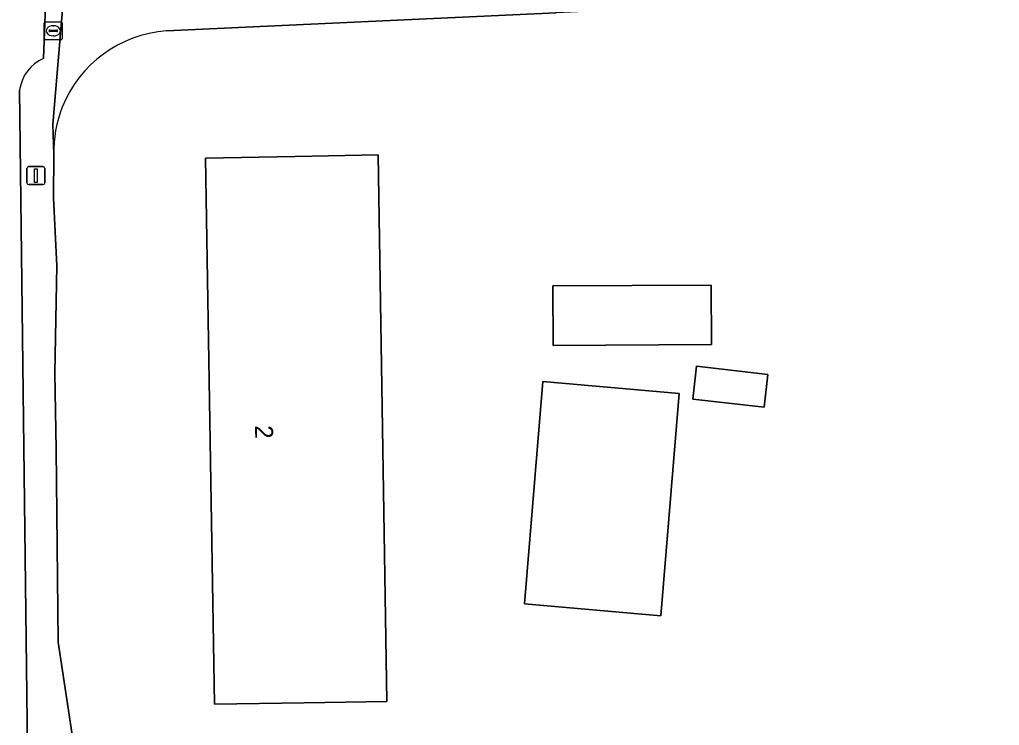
# Model space of a CAD drawing. Extents: x 163859 to 164644, y 379566 to 382155.
# Drawn here: x 164443.9 to 164498.5, y 381567 to 381606.4 of the extents above; entities that cross this region are included whole.
import ezdxf

# ---------------------------------------------------------------- set-up
doc = ezdxf.new("R2010")
doc.units = 0
for name, color, linetype in [('IMGEO_Brandkraan', 7, 'Continuous'), ('IMGEO_Erf', 7, 'Continuous'), ('IMGEO_Groenvoorziening', 7, 'Continuous'), ('IMGEO_Lichtmast', 7, 'Continuous'), ('IMGEO_Pand', 7, 'Continuous'), ('IMGEO_Pand_nummerreeks', 7, 'Continuous'), ('IMGEO_Rijbaan_lokaal_gesloten', 7, 'Continuous')]:
    doc.layers.add(name, color=color, linetype=linetype)

msp = doc.modelspace()

# ---------------------------------------------------------------- linework, layer by layer
at = {"layer": 'IMGEO_Brandkraan'}
for p, q in [((164445.336, 381606.254), (164446.188, 381606.254)), ((164445.261, 381605.328), (164445.261, 381606.18)), ((164445.52, 381605.748), (164445.52, 381605.76)), ((164445.958, 381605.711), (164445.56, 381605.711)), ((164445.563, 381605.797), (164445.961, 381605.797)), ((164445.749, 381606.034), (164445.774, 381606.034)), ((164446.004, 381605.76), (164446.004, 381605.748)), ((164446.262, 381606.18), (164446.262, 381605.328)), ((164446.188, 381605.254), (164445.336, 381605.254)), ((164445.772, 381605.474), (164445.747, 381605.474))]:
    msp.add_line(p, q, dxfattribs=at)
for points in [[(164445.336, 381606.254), (164446.188, 381606.254)], [(164445.261, 381605.328), (164445.261, 381606.18)], [(164446.262, 381606.18), (164446.262, 381605.328)], [(164446.188, 381605.254), (164445.336, 381605.254)]]:
    msp.add_lwpolyline(points, dxfattribs=at)
for centre, radius, start, end in [((164445.338, 381606.178), 0.0765, 91.552, 178.448), ((164445.338, 381606.178), 0.0765, 91.552, 178.448), ((164446.186, 381606.178), 0.0765, 1.552, 88.448), ((164446.186, 381606.178), 0.0765, 1.552, 88.448), ((164445.56, 381605.757), 0.0403, 85.8775, 175.7526), ((164445.557, 381605.747), 0.0366, 178.938, 274.7102), ((164445.961, 381605.754), 0.043, 264.8664, 352.4533), ((164445.965, 381605.759), 0.0386, 1.7309, 96.639), ((164445.338, 381605.33), 0.0765, 181.552, 268.448), ((164445.338, 381605.33), 0.0765, 181.552, 268.448), ((164446.186, 381605.33), 0.0765, 271.552, 358.448), ((164446.186, 381605.33), 0.0765, 271.552, 358.448)]:
    msp.add_arc(centre, radius, start, end, dxfattribs=at)
for centre, major_axis, ratio, start_param, end_param in [((164445.748, 381605.754), (-0.387, 0.002), 0.722429, 4.712389, 7.853982), ((164445.773, 381605.754), (-0.39, 0.002), 0.717154, 1.570796, 4.712389)]:
    msp.add_ellipse(centre, major_axis=major_axis, ratio=ratio, start_param=start_param, end_param=end_param, dxfattribs=at)
at = {"layer": 'IMGEO_Erf'}
for points in [[(164504.238, 381639.639), (164497.717, 381638.341), (164491.561, 381625.418), (164500, 381625.257), (164511.742, 381625.032), (164511.845, 381616.048), (164500, 381616.257), (164491.641, 381616.405), (164491.641, 381607.592), (164473.792, 381606.759), (164452.065, 381605.746)], [(164445.787, 381598.852), (164445.764, 381596.44), (164445.965, 381592.66), (164445.846, 381586.661), (164445.919, 381582.439), (164446.039, 381571.665), (164447.241, 381563.679), (164447.524, 381549.09), (164447.578, 381546.287), (164449.661, 381543.607), (164450.081, 381523.979), (164450.552, 381522.923), (164450.681, 381517.673), (164450.068, 381516.565), (164449.908, 381509.122), (164450.098, 381507.688), (164450.009, 381500), (164449.956, 381495.455)]]:
    msp.add_lwpolyline(points, dxfattribs=at)
for points in [[(164464.351, 381568.368), (164459.743, 381568.296), (164454.743, 381568.217), (164454.239, 381598.654), (164459.239, 381598.748), (164463.871, 381598.836)], [(164473.635, 381588.213), (164473.617, 381591.535), (164482.435, 381591.583), (164482.453, 381588.26)], [(164481.413, 381585.223), (164481.623, 381587.058), (164485.596, 381586.603), (164485.386, 381584.768)], [(164479.627, 381573.138), (164472.036, 381573.807), (164473.058, 381586.206), (164480.65, 381585.536)]]:
    msp.add_lwpolyline(points, close=True, dxfattribs=at)
for centre, radius, start, end in [((164452.548, 381599.001), 6.762, 94.0969, 158.32), ((164452.524, 381599.004), 6.739, 158.2733, 181.2961)]:
    msp.add_arc(centre, radius, start, end, dxfattribs=at)
at = {"layer": 'IMGEO_Groenvoorziening'}
for points in [[(164452.065, 381605.746), (164473.792, 381606.759), (164473.688, 381609.802), (164473.548, 381613.906), (164483.66, 381617.038), (164498.403, 381643.097)], [(164446.039, 381571.665), (164445.919, 381582.439), (164445.846, 381586.661), (164445.965, 381592.66), (164445.764, 381596.44), (164445.787, 381598.852), (164445.729, 381600.527), (164446.54, 381610.042), (164445.386, 381608.654), (164445.211, 381604.21)], [(164446.54, 381610.042), (164445.729, 381600.527), (164445.787, 381598.852)], [(164443.883, 381602.468), (164444.8, 381525.846), (164448.319, 381522.868), (164450.552, 381522.923), (164450.081, 381523.979), (164448.502, 381523.829), (164448.175, 381543.122), (164445.82, 381545.263), (164445.543, 381563.461), (164447.241, 381563.679), (164446.039, 381571.665)]]:
    msp.add_lwpolyline(points, dxfattribs=at)
for centre, radius, start, end in [((164452.548, 381599.001), 6.762, 94.0969, 158.32), ((164446.127, 381602.134), 2.269, 113.8211, 171.5393), ((164452.524, 381599.004), 6.739, 158.2733, 181.2961)]:
    msp.add_arc(centre, radius, start, end, dxfattribs=at)
at = {"layer": 'IMGEO_Lichtmast'}
for p, q in [((164444.294, 381597.282), (164444.294, 381598.082)), ((164444.294, 381598.082), (164444.294, 381597.282)), ((164444.394, 381598.182), (164445.184, 381598.182)), ((164445.184, 381598.182), (164444.394, 381598.182)), ((164445.284, 381598.082), (164445.284, 381597.282)), ((164445.284, 381597.282), (164445.284, 381598.082)), ((164445.184, 381597.182), (164444.394, 381597.182)), ((164444.394, 381597.182), (164445.184, 381597.182))]:
    msp.add_line(p, q, dxfattribs=at)
msp.add_lwpolyline([(164444.714, 381598.057), (164444.864, 381598.057), (164444.864, 381597.307), (164444.714, 381597.307), (164444.714, 381598.057)], dxfattribs=at)
for centre, start, end in [((164444.394, 381598.082), 90, 180), ((164444.394, 381598.082), 90, 180), ((164445.184, 381598.082), 0, 90), ((164445.184, 381598.082), 360, 90), ((164444.394, 381597.282), 180, 270), ((164444.394, 381597.282), 180, 270), ((164445.184, 381597.282), 270, 0), ((164445.184, 381597.282), 270, 0)]:
    msp.add_arc(centre, 0.1, start, end, dxfattribs=at)
at = {"layer": 'IMGEO_Pand'}
for points in [[(164454.743, 381568.217), (164459.743, 381568.296), (164464.351, 381568.368), (164463.871, 381598.836), (164459.239, 381598.748), (164454.239, 381598.654)], [(164473.617, 381591.535), (164473.635, 381588.213), (164482.453, 381588.26), (164482.435, 381591.583)], [(164481.413, 381585.223), (164485.386, 381584.768), (164485.596, 381586.603), (164481.623, 381587.058)], [(164479.627, 381573.138), (164480.65, 381585.536), (164473.058, 381586.206), (164472.036, 381573.807)]]:
    msp.add_lwpolyline(points, close=True, dxfattribs=at)
at = {"layer": 'IMGEO_Rijbaan_lokaal_gesloten'}
for points in [[(164445.211, 381604.21), (164445.386, 381608.654)], [(164445.416, 381474.386), (164445.363, 381478.812), (164445.247, 381488.484), (164445.109, 381500), (164444.923, 381515.568), (164444.8, 381525.846), (164443.883, 381602.468)]]:
    msp.add_lwpolyline(points, dxfattribs=at)
msp.add_arc((164446.127, 381602.134), 2.269, 113.8211, 171.5393, dxfattribs=at)

# ---------------------------------------------------------------- texts
at = {"layer": 'IMGEO_Pand_nummerreeks'}
msp.add_text('2', height=1, rotation=270.9487, dxfattribs=at).set_placement((164457.007, 381583.755))

doc.saveas('drawing.dxf')
